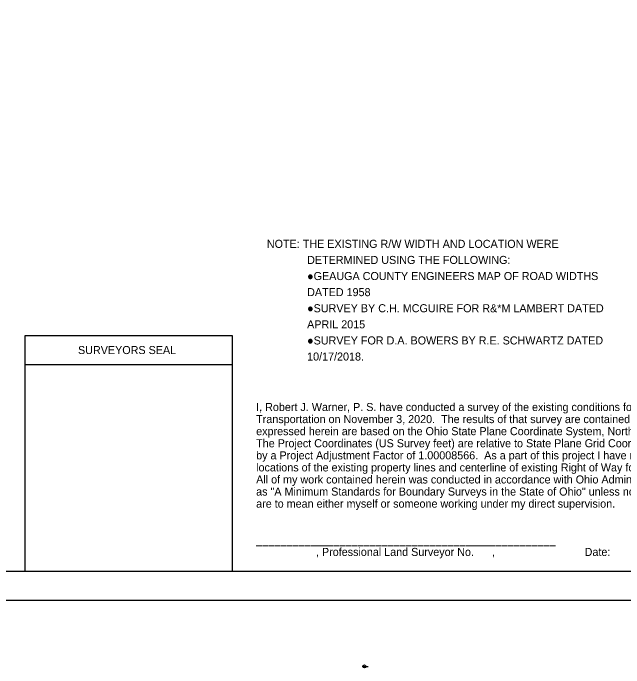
# Model space of a CAD drawing. Extents: x -6.7 to 34, y -1.6 to 22.
# Drawn here: x 17.08 to 27.7, y -1.18 to 10.21 of the extents above; entities that cross this region are included whole.
import ezdxf

# ---------------------------------------------------------------- set-up
doc = ezdxf.new("R2010")
doc.units = 0
for name, color, linetype in [('Default', 7, 'Continuous'), ('SH_Border', 7, 'Continuous'), ('SH_Cut_Line', 7, 'Continuous'), ('SH_Named_Boundary', 7, 'Continuous'), ('SH_Text', 7, 'Continuous')]:
    doc.layers.add(name, color=color, linetype=linetype)

msp = doc.modelspace()

# ---------------------------------------------------------------- linework, layer by layer
at = {"layer": 'Default'}
for p, q in [((23.163, -1.152), (23.216, -1.152)), ((23.19, -1.152), (23.254, -1.152))]:
    msp.add_line(p, q, dxfattribs=at)
msp.add_circle((23.189, -1.152), 0.026, dxfattribs=at)
at = {"layer": 'SH_Border'}
msp.add_lwpolyline([(1.5, 21.5), (33.5, 21.5), (33.5, 0.5), (1.5, 0.5)], close=True, dxfattribs=at)
at = {"layer": 'SH_Cut_Line'}
msp.add_line((17.288, 4.1), (20.888, 4.1), dxfattribs=at)
msp.add_lwpolyline([(17.288, 4.6), (20.888, 4.6), (20.888, 0.5), (17.288, 0.5)], close=True, dxfattribs=at)
at = {"layer": 'SH_Named_Boundary'}
msp.add_lwpolyline([(0, 0), (34, 0), (34, 22), (0, 22)], close=True, dxfattribs=at)

# ---------------------------------------------------------------- texts
at = {"layer": 'Default'}
for s, p in [('154', (23.186, -1.162)), ('2', (23.188, -1.146)), ('108471_RC001', (23.222, -1.146)), ('1:200', (23.222, -1.162))]:
    msp.add_text(s, height=0.00328, dxfattribs=at).set_placement(p)
at = {"layer": 'SH_Cut_Line'}
msp.add_text('SURVEYORS SEAL', height=0.14, dxfattribs=at).set_placement((18.209, 4.28))
at = {"layer": 'SH_Text'}
for s, p in [('NOTE: THE EXISTING R/W WIDTH AND LOCATION WERE ', (21.493, 6.127)), ('DETERMINED USING THE FOLLOWING:', (22.193, 5.847)), ('●GEAUGA COUNTY ENGINEERS MAP OF ROAD WIDTHS ', (22.193, 5.567)), ('DATED 1958', (22.193, 5.287)), ('●SURVEY BY C.H. MCGUIRE FOR R&*M LAMBERT DATED ', (22.193, 5.007)), ('APRIL 2015', (22.193, 4.727)), ('●SURVEY FOR D.A. BOWERS BY R.E. SCHWARTZ DATED ', (22.193, 4.447)), ('10/17/2018.', (22.193, 4.167)), ('I, Robert J. Warner, P. S. have conducted a survey of the existing conditions for the Ohio Department of', (21.307, 3.289)), ('Transportation on November 3, 2020.  The results of that survey are contained herein.  The horizontal coordinates', (21.307, 3.079)), ('expressed herein are based on the Ohio State Plane Coordinate System, North Zone on NAD 83 (2011) datum.', (21.307, 2.869)), ('The Project Coordinates (US Survey feet) are relative to State Plane Grid Coordinates (US Survey feet)', (21.307, 2.659)), ('by a Project Adjustment Factor of 1.00008566.  As a part of this project I have reestablished the', (21.307, 2.449)), ('locations of the existing property lines and centerline of existing Right of Way for property takes contained herein.  ', (21.307, 2.239)), ('All of my work contained herein was conducted in accordance with Ohio Administrative Code 4733-37 commonly known', (21.307, 2.029)), ('as "A Minimum Standards for Boundary Surveys in the State of Ohio" unless noted.  The words I and my as used herein', (21.307, 1.819)), ('are to mean either myself or someone working under my direct supervision.', (21.307, 1.609)), ('__________________________________________________', (21.307, 0.979)), ('                    , Professional Land Surveyor No.      ,                              Date:                ', (21.307, 0.769))]:
    msp.add_text(s, height=0.14, dxfattribs=at).set_placement(p)

doc.saveas('drawing.dxf')
